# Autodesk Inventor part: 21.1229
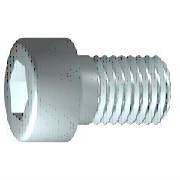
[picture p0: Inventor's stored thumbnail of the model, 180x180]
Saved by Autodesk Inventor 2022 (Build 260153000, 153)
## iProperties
Created: 2006-02
Part Number: 21.1229
Material: Steel, Mild
Description: M4X12 SHCS
Document SubType Name: Modeling
Standard: DIN 7984
Designer: Andy Moles
Standards Organization: DIN
Language: en-US
Size Designation: M4 x 12
Categories: <MemberInstance><Categories><Category DisplayName="Fasteners" InternalName="e4da775c-781d-43d5-af7c-5136215cf5a6" Mnemonic="FSTN"><Category DisplayName="Bolts"
Density: 7.85 g/cm^3
Mass: 1.90382 g
Surface Area: 3.03485 cm^2
Volume: 0.242524 cm^3
Vendor: S
Appearance: Zinc
IsCustomPart: 1
Title: M4x12 SHCS ZINC PLATED
Author: Andy Moles
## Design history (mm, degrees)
sketch "Sketch1"
  geometry: L1 (0.333, 0)-(12, 0); L2 (12, 0)-(12, 2); L3 (12, 2)-(2.1, 2); L4 (2.1, 2)-(1.67, 2); L5 (1.67, 2)-(0, 2); L6 (0, 2)-(0, 3.5); L7 (0, 3.5)-(-2.8, 3.5); L8 (-2.8, 3.5)-(-2.8, 1.443); L9 (-2.8, 1.443)-(-0.5, 1.443); L10 (-0.5, 1.443)-(0.333, 0); L11 (-4.28, 0)-(16.44, 0) reference; L12 (0, -0.35)-(0, 4.55) reference; L13 (2.1, 2)-(0, 2)
  constraints: 22 end point, 6 parallel, 2 collinear, 2 perpendicular, 1 horizontal, 1 point on line
  dimensions: "d1" = 9.9 distance from line of L3.end L2 (= GEL); "d2" = 0.42952 distance of L4.end L3.end (computed from GAL); "d3" = 2.8 distance between parallel lines of L8 L6 (= KOH); "d4" = 2.3 distance of L8.end L9.end (= INTI); "d5" = 60 deg angle of L10 L1; "d6" = 4 diameter of L3 L1 (= GD); "d7" = 4 diameter of L5 L1 (= BDM); "d8" = 2.88675 diameter of L9 L1 (= 1.1547 x SW); "d9" = 7 diameter of L7 L1 (= KOD); "d26" = 12 distance between parallel lines of L12 L2 (= NLG)
revolve "Body" sketch "Sketch1" stored, may be unused: angle "d10" = 90 deg
sketch "Sketch2"
  geometry: L1 (0, -4.2)-(0, 5.6) reference; L2 (-4.2, 0)-(5.6, 0) reference; L3 (1.443, 0)-(0.722, -1.25); L4 (0.722, -1.25)-(-0.722, -1.25); L5 (-0.722, -1.25)-(-1.443, 0); L6 (-1.443, 0)-(-0.722, 1.25); L7 (-0.722, 1.25)-(0.722, 1.25); L8 (0.722, 1.25)-(1.443, 0); 2 further points
  constraints: 12 end point, 1 coincident, 1 horizontal alignment, 1 point on line, 12 other
extrude "Slot" join sketch "Sketch2" stored distance "d11" = 10; taper "d12" = 0 deg
workplane "Work Plane1"
body "Solid1"
fillet "Fillet1" dims "d17" = 0.4 (= RR)
feature "Thread" dims "d13" = 12, "d14" = 0
chamfer "Chamfer1" distance "d15" = 0.42941 (= -0.5 x SPD + 0.5 x GD); stored, may be unused: second distance "d16" = 0.42941 (= GUL), angle "d27" = 45 deg
other parameters: "GD" = 4 (= NND) [user parameter; used in 2 equation terms], "NLG" = 12 [user parameter; used in 1 equation term], "GEL" = 9.9 [user parameter; used in 1 equation term], "KOD" = 7 [user parameter; used in 1 equation term], "KOH" = 2.8 [user parameter; used in 1 equation term], "INTI" = 2.3 [user parameter; used in 1 equation term], "GAL" = 0.42941 (= 0.61345 x PTC) [user parameter; used in 1 equation term], "GUL" = 0.42941 (= 0.61345 x PTC) [user parameter; used in 1 equation term], "BDM" = 4 (= NND) [user parameter; used in 1 equation term], "SW" = 2.5 [user parameter; used in 2 equation terms], "RR" = 0.4 [user parameter; used in 1 equation term], "SPD" = 3.14117 (= NND - 1.2269 x PTC) [user parameter; used in 1 equation term], "d19" = 0, "d28" = 0, "d29" = 0, "TOA" = 30 deg [user parameter], "GD1" = 3.14117 (= THREADDIA - 1.2269 x PTC) [user parameter], "THREADDIA" = 4 [user parameter; used in 1 equation term], "FAWI" = 45 deg [user parameter], "ANG" = 120 deg [user parameter], "TPU" = 14.28571 (computed from PTC) [user parameter], "PTC" = 0.7 [user parameter; used in 5 equation terms], "NND" = 4 [user parameter; used in 3 equation terms], "E0" = 2.8875 (= 1.155 x SW) [user parameter]
